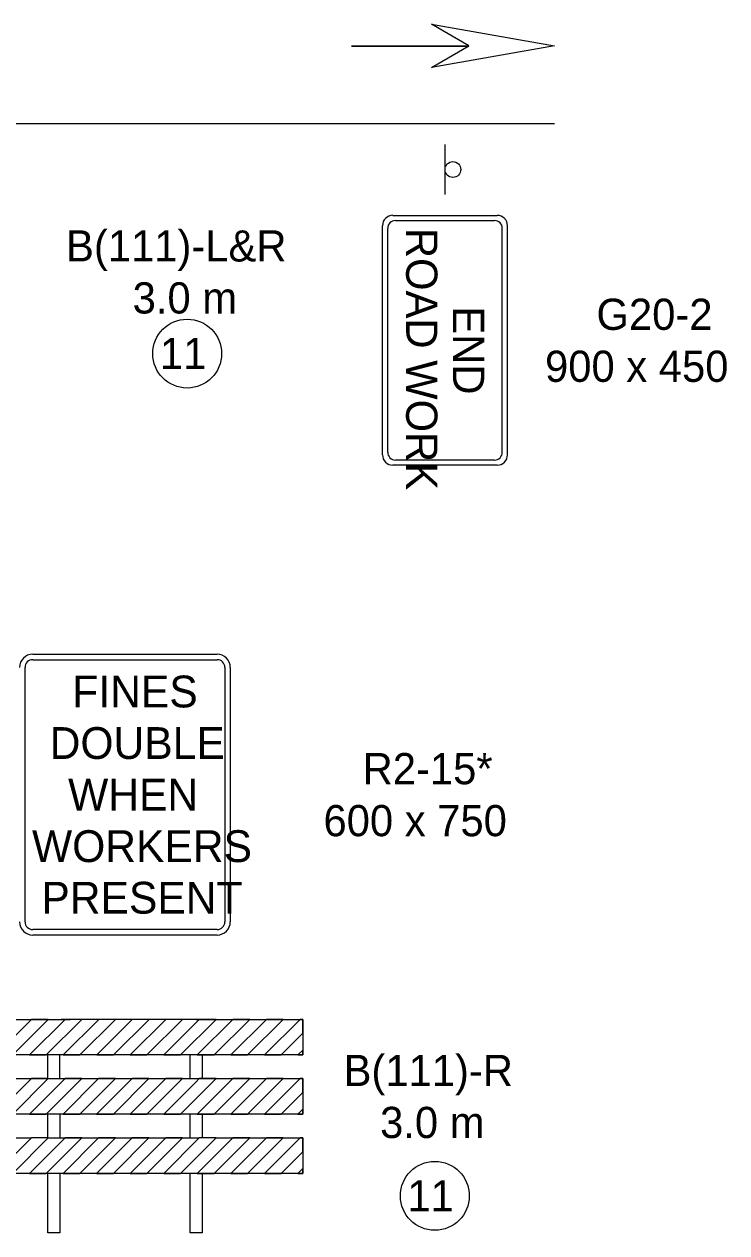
# Model space of a CAD drawing. Extents: x 49991.4 to 50021, y 49987.6 to 50011.4.
# Drawn here: x 50012.184 to 50013.534, y 49991.008 to 49993.332 of the extents above; entities that cross this region are included whole.
import ezdxf

# ---------------------------------------------------------------- set-up
doc = ezdxf.new("R2010")
doc.units = 0
for name, color, linetype in [('Level 1', 7, 'Continuous'), ('Level 2', 7, 'Continuous'), ('Level 3', 7, 'Continuous')]:
    doc.layers.add(name, color=color, linetype=linetype)

# ---------------------------------------------------------------- blocks, each defined once
blk = doc.blocks.new('G20-2')
at = {"layer": 'Level 1'}
for p, q in [((0.2197, 0.1196), (-0.2203, 0.1196)), ((-0.2403, -0.1004), (-0.2403, 0.0996)), ((-0.2303, -0.0954), (-0.2303, 0.0946)), ((0.2147, 0.1096), (-0.2153, 0.1096)), ((0.2297, 0.0946), (0.2297, -0.0954)), ((0.2397, 0.0996), (0.2397, -0.1004)), ((0.2147, -0.1104), (-0.2153, -0.1104)), ((0.2196, -0.1204), (-0.2204, -0.1204))]:
    blk.add_line(p, q, dxfattribs=at)
for centre, radius, start, end in [((-0.2203, 0.0996), 0.02, 90, 180), ((0.2197, 0.0996), 0.02, 360, 90), ((-0.2153, 0.0946), 0.015, 90, 180), ((0.2147, 0.0946), 0.015, 360, 90), ((-0.2204, -0.1004), 0.02, 180, 270), ((-0.2153, -0.0954), 0.015, 180, 270), ((0.2147, -0.0954), 0.015, 270, 360), ((0.2196, -0.1004), 0.02, 270, 360)]:
    blk.add_arc(centre, radius, start, end, dxfattribs=at)
for s, p in [('END', (-0.0655, 0.015)), ('ROAD WORK', (-0.2162, -0.075))]:
    blk.add_text(s, height=0.06, rotation=360, dxfattribs=at).set_placement(p)

msp = doc.modelspace()

# ---------------------------------------------------------------- linework, layer by layer
at = {"layer": 'Level 1'}
for p, q in [((50012.8131, 49993.2905), (50013.039, 49993.2905)), ((50012.8131, 49993.2901), (50013.039, 49993.2901)), ((50013.2032, 49993.1404), (50011.4032, 49993.1404)), ((50012.9929, 49993.0044), (50012.9929, 49993.1004)), ((50012.2007, 49992.1205), (50012.5551, 49992.1205)), ((50012.2007, 49992.11), (50012.5551, 49992.11)), ((50012.3779, 49992.1205), (50012.3779, 49992.1205)), ((50012.1859, 49991.6058), (50012.1859, 49992.0952)), ((50012.5699, 49992.0952), (50012.5699, 49991.6058)), ((50012.5804, 49992.0952), (50012.5804, 49991.6058)), ((50012.5551, 49991.591), (50012.2007, 49991.591)), ((50012.5551, 49991.5805), (50012.2007, 49991.5805)), ((50012.1301, 49991.3498), (50012.1985, 49991.4182)), ((50012.1985, 49991.4182), (50012.1301, 49991.3498)), ((50012.1623, 49991.3498), (50012.2307, 49991.4182)), ((50012.1623, 49991.3498), (50012.2307, 49991.4182)), ((50012.1946, 49991.3498), (50012.2629, 49991.4182)), ((50012.2268, 49991.3498), (50012.2952, 49991.4182)), ((50012.2411, 49991.4182), (50012.2724, 49991.4182)), ((50012.5004, 49991.4182), (50012.2554, 49991.4182)), ((50012.2592, 49991.3498), (50012.3276, 49991.4182)), ((50012.2914, 49991.3498), (50012.3598, 49991.4182)), ((50012.3236, 49991.3498), (50012.392, 49991.4182)), ((50012.3558, 49991.3498), (50012.4242, 49991.4182)), ((50012.3881, 49991.3498), (50012.4564, 49991.4182)), ((50012.4203, 49991.3498), (50012.4886, 49991.4182)), ((50012.4525, 49991.3498), (50012.5208, 49991.4182)), ((50012.5208, 49991.4182), (50012.481, 49991.4182)), ((50012.4847, 49991.3498), (50012.5531, 49991.4182)), ((50012.5169, 49991.3498), (50012.5853, 49991.4182)), ((50012.5853, 49991.4182), (50012.5169, 49991.3498)), ((50012.5492, 49991.3498), (50012.6176, 49991.4182)), ((50012.5492, 49991.3498), (50012.6176, 49991.4182)), ((50012.5814, 49991.3498), (50012.6498, 49991.4182)), ((50012.6498, 49991.4182), (50012.5814, 49991.3498)), ((50012.6136, 49991.3498), (50012.682, 49991.4182)), ((50012.6136, 49991.3498), (50012.682, 49991.4182)), ((50012.6459, 49991.3498), (50012.7143, 49991.4182)), ((50012.7143, 49991.4182), (50012.6459, 49991.3498)), ((50012.6781, 49991.3498), (50012.7199, 49991.3916)), ((50012.6781, 49991.3498), (50012.7199, 49991.3916)), ((50012.2525, 49991.3043), (50012.2525, 49991.3498)), ((50012.5033, 49991.3043), (50012.5033, 49991.3498)), ((50012.7104, 49991.3498), (50012.7199, 49991.3593)), ((50012.7199, 49991.3593), (50012.7104, 49991.3498)), ((50012.1301, 49991.2359), (50012.1985, 49991.3043)), ((50012.1985, 49991.3043), (50012.1301, 49991.2359)), ((50012.1623, 49991.2359), (50012.2307, 49991.3043)), ((50012.1623, 49991.2359), (50012.2307, 49991.3043)), ((50012.1946, 49991.2359), (50012.2629, 49991.3043)), ((50012.2268, 49991.2359), (50012.2952, 49991.3043)), ((50012.259, 49991.2359), (50012.3274, 49991.3043)), ((50012.2913, 49991.2359), (50012.3597, 49991.3043)), ((50012.3235, 49991.2359), (50012.3919, 49991.3043)), ((50012.3557, 49991.2359), (50012.4241, 49991.3043)), ((50012.388, 49991.2359), (50012.4564, 49991.3043)), ((50012.4202, 49991.2359), (50012.4886, 49991.3043)), ((50012.4525, 49991.2359), (50012.5147, 49991.2981)), ((50012.5147, 49991.2659), (50012.5531, 49991.3043)), ((50012.5147, 49991.2981), (50012.5208, 49991.3043)), ((50012.5169, 49991.2359), (50012.5853, 49991.3043)), ((50012.5853, 49991.3043), (50012.5169, 49991.2359)), ((50012.5492, 49991.2359), (50012.6176, 49991.3043)), ((50012.5492, 49991.2359), (50012.6176, 49991.3043)), ((50012.5814, 49991.2359), (50012.6498, 49991.3043)), ((50012.6498, 49991.3043), (50012.5814, 49991.2359)), ((50012.6136, 49991.2359), (50012.682, 49991.3043)), ((50012.6136, 49991.2359), (50012.682, 49991.3043)), ((50012.6459, 49991.2359), (50012.7143, 49991.3043)), ((50012.7143, 49991.3043), (50012.6459, 49991.2359)), ((50012.6781, 49991.2359), (50012.7199, 49991.2776)), ((50012.6781, 49991.2359), (50012.7199, 49991.2776)), ((50012.4847, 49991.2359), (50012.5147, 49991.2659)), ((50012.7104, 49991.2359), (50012.7199, 49991.2454)), ((50012.7199, 49991.2454), (50012.7104, 49991.2359)), ((50012.1301, 49991.1219), (50012.1985, 49991.1903)), ((50012.1985, 49991.1903), (50012.1301, 49991.1219)), ((50012.1623, 49991.1219), (50012.2307, 49991.1903)), ((50012.1623, 49991.1219), (50012.2307, 49991.1903)), ((50012.1946, 49991.1219), (50012.2629, 49991.1903)), ((50012.2629, 49991.1903), (50012.1946, 49991.1219)), ((50012.2268, 49991.1219), (50012.2952, 49991.1903)), ((50012.2268, 49991.1219), (50012.2952, 49991.1903)), ((50012.259, 49991.1219), (50012.3274, 49991.1903)), ((50012.3274, 49991.1903), (50012.259, 49991.1219)), ((50012.2913, 49991.1219), (50012.3597, 49991.1903)), ((50012.2913, 49991.1219), (50012.3597, 49991.1903)), ((50012.3235, 49991.1219), (50012.3919, 49991.1903)), ((50012.3919, 49991.1903), (50012.3235, 49991.1219)), ((50012.3557, 49991.1219), (50012.4241, 49991.1903)), ((50012.3557, 49991.1219), (50012.4241, 49991.1903)), ((50012.388, 49991.1219), (50012.4564, 49991.1903)), ((50012.4564, 49991.1903), (50012.388, 49991.1219)), ((50012.4202, 49991.1219), (50012.4886, 49991.1903)), ((50012.4202, 49991.1219), (50012.4886, 49991.1903)), ((50012.4525, 49991.1219), (50012.5208, 49991.1903)), ((50012.5208, 49991.1903), (50012.4525, 49991.1219)), ((50012.4847, 49991.1219), (50012.5531, 49991.1903)), ((50012.4847, 49991.1219), (50012.5531, 49991.1903)), ((50012.5169, 49991.1219), (50012.5853, 49991.1903)), ((50012.5853, 49991.1903), (50012.5169, 49991.1219)), ((50012.5492, 49991.1219), (50012.6176, 49991.1903)), ((50012.5492, 49991.1219), (50012.6176, 49991.1903)), ((50012.5814, 49991.1219), (50012.6498, 49991.1903)), ((50012.6498, 49991.1903), (50012.5814, 49991.1219)), ((50012.6136, 49991.1219), (50012.682, 49991.1903)), ((50012.6136, 49991.1219), (50012.682, 49991.1903)), ((50012.6459, 49991.1219), (50012.7143, 49991.1903)), ((50012.7143, 49991.1903), (50012.6459, 49991.1219)), ((50012.6781, 49991.1219), (50012.7199, 49991.1637)), ((50012.6781, 49991.1219), (50012.7199, 49991.1637)), ((50012.7104, 49991.1219), (50012.7199, 49991.1315)), ((50012.7199, 49991.1315), (50012.7104, 49991.1219))]:
    msp.add_line(p, q, dxfattribs=at)
msp.add_lwpolyline([(50012.9667, 49993.3321), (50013.2032, 49993.2905), (50012.9667, 49993.2485), (50013.0389, 49993.2905)], close=True, dxfattribs=at)
for points in [[(50012.5147, 49991.3498), (50012.0359, 49991.3498), (50012.0359, 49991.4182), (50012.2411, 49991.4182)], [(50012.2952, 49991.4182), (50012.2724, 49991.4182), (50012.2629, 49991.4182), (50012.1946, 49991.3498), (50012.2268, 49991.3498), (50012.2952, 49991.4182)], [(50012.2307, 49991.4182), (50012.1985, 49991.4182)], [(50012.3598, 49991.4182), (50012.3276, 49991.4182), (50012.2592, 49991.3498), (50012.2914, 49991.3498), (50012.3598, 49991.4182)], [(50012.4242, 49991.4182), (50012.392, 49991.4182), (50012.3236, 49991.3498), (50012.3558, 49991.3498), (50012.4242, 49991.4182)], [(50012.4886, 49991.4182), (50012.481, 49991.4182), (50012.4564, 49991.4182), (50012.3881, 49991.3498), (50012.4203, 49991.3498), (50012.4886, 49991.4182)], [(50012.4525, 49991.3498), (50012.4847, 49991.3498), (50012.5531, 49991.4182), (50012.5208, 49991.4182), (50012.4525, 49991.3498)], [(50012.5147, 49991.4182), (50012.7199, 49991.4182), (50012.7199, 49991.3498), (50012.5147, 49991.3498)], [(50012.6176, 49991.4182), (50012.5853, 49991.4182)], [(50012.682, 49991.4182), (50012.6498, 49991.4182)], [(50012.7199, 49991.3916), (50012.7199, 49991.4182), (50012.7143, 49991.4182)], [(50012.2297, 49991.3042), (50012.2297, 49991.3498)], [(50012.5169, 49991.3498), (50012.5492, 49991.3498)], [(50012.5261, 49991.3498), (50012.5261, 49991.3043)], [(50012.5814, 49991.3498), (50012.6136, 49991.3498)], [(50012.6459, 49991.3498), (50012.6781, 49991.3498)], [(50012.7104, 49991.3498), (50012.7199, 49991.3498), (50012.7199, 49991.3593)], [(50012.5147, 49991.3043), (50012.7199, 49991.3043), (50012.7199, 49991.2359), (50012.0359, 49991.2359), (50012.0359, 49991.3043), (50012.5147, 49991.3043)], [(50012.2952, 49991.3043), (50012.2629, 49991.3043), (50012.1946, 49991.2359), (50012.2268, 49991.2359), (50012.2952, 49991.3043)], [(50012.2307, 49991.3043), (50012.1985, 49991.3043)], [(50012.3597, 49991.3043), (50012.3274, 49991.3043), (50012.259, 49991.2359), (50012.2913, 49991.2359), (50012.3597, 49991.3043)], [(50012.4241, 49991.3043), (50012.3919, 49991.3043), (50012.3235, 49991.2359), (50012.3557, 49991.2359), (50012.4241, 49991.3043)], [(50012.4886, 49991.3043), (50012.4564, 49991.3043), (50012.388, 49991.2359), (50012.4202, 49991.2359), (50012.4886, 49991.3043)], [(50012.4525, 49991.2359), (50012.4847, 49991.2359), (50012.5147, 49991.2659), (50012.5531, 49991.3043), (50012.5261, 49991.3043), (50012.5208, 49991.3043), (50012.5147, 49991.2981), (50012.4525, 49991.2359)], [(50012.6176, 49991.3043), (50012.5853, 49991.3043)], [(50012.682, 49991.3043), (50012.6498, 49991.3043)], [(50012.7199, 49991.2776), (50012.7199, 49991.3043), (50012.7143, 49991.3043)], [(50012.2297, 49991.1903), (50012.2297, 49991.2359)], [(50012.2525, 49991.2359), (50012.2525, 49991.1903)], [(50012.5033, 49991.1903), (50012.5033, 49991.2359)], [(50012.5169, 49991.2359), (50012.5492, 49991.2359)], [(50012.5261, 49991.2359), (50012.5261, 49991.1903)], [(50012.5814, 49991.2359), (50012.6136, 49991.2359)], [(50012.6459, 49991.2359), (50012.6781, 49991.2359)], [(50012.7104, 49991.2359), (50012.7199, 49991.2359), (50012.7199, 49991.2454)], [(50012.5531, 49991.1903), (50012.7199, 49991.1903), (50012.7199, 49991.1219), (50012.0359, 49991.1219), (50012.0359, 49991.1903), (50012.1985, 49991.1903)], [(50012.2307, 49991.1903), (50012.1985, 49991.1903)], [(50012.2307, 49991.1903), (50012.5208, 49991.1903)], [(50012.2952, 49991.1903), (50012.2629, 49991.1903)], [(50012.3597, 49991.1903), (50012.3274, 49991.1903)], [(50012.4241, 49991.1903), (50012.3919, 49991.1903)], [(50012.4886, 49991.1903), (50012.4564, 49991.1903)], [(50012.5531, 49991.1903), (50012.5208, 49991.1903)], [(50012.6176, 49991.1903), (50012.5853, 49991.1903)], [(50012.682, 49991.1903), (50012.6498, 49991.1903)], [(50012.7199, 49991.1637), (50012.7199, 49991.1903), (50012.7143, 49991.1903)], [(50012.1946, 49991.1219), (50012.2268, 49991.1219)], [(50012.2525, 49991.1218), (50012.2525, 49991.0078), (50012.2297, 49991.0078), (50012.2297, 49991.1218)], [(50012.259, 49991.1219), (50012.2913, 49991.1219)], [(50012.3235, 49991.1219), (50012.3557, 49991.1219)], [(50012.388, 49991.1219), (50012.4202, 49991.1219)], [(50012.4525, 49991.1219), (50012.4847, 49991.1219)], [(50012.5261, 49991.1218), (50012.5261, 49991.0078), (50012.5033, 49991.0078), (50012.5033, 49991.1218)], [(50012.5169, 49991.1219), (50012.5492, 49991.1219)], [(50012.5814, 49991.1219), (50012.6136, 49991.1219)], [(50012.6459, 49991.1219), (50012.6781, 49991.1219)], [(50012.7104, 49991.1219), (50012.7199, 49991.1219), (50012.7199, 49991.1315)]]:
    msp.add_lwpolyline(points, dxfattribs=at)
msp.add_circle((50013.0081, 49993.0525), 0.0152, dxfattribs=at)
for centre, radius, start, end in [((50012.2007, 49992.0952), 0.0253, 90, 180), ((50012.2007, 49992.0952), 0.0148, 90, 180), ((50012.5551, 49992.0952), 0.0253, 0, 90), ((50012.5551, 49992.0952), 0.0148, 0, 90), ((50012.2007, 49991.6058), 0.0253, 180, 270), ((50012.2007, 49991.6058), 0.0148, 180, 270), ((50012.5551, 49991.6058), 0.0148, 270, 360), ((50012.5551, 49991.6058), 0.0253, 270, 360)]:
    msp.add_arc(centre, radius, start, end, dxfattribs=at)
at = {"layer": 'Level 2'}
for centre in [(50012.4975, 49992.6986), (50012.9734, 49991.0789)]:
    msp.add_circle(centre, 0.0662, dxfattribs=at)

# ---------------------------------------------------------------- block references
at = {"layer": 'Level 3', "xscale": 1.001, "yscale": 1.001, "rotation": -90.00000000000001}
msp.add_blockref('G20-2', (50012.9933, 49992.7239), dxfattribs=at)

# ---------------------------------------------------------------- texts
at = {"layer": 'Level 1'}
for s, p in [('FINES', (50012.2768, 49992.0182)), ('DOUBLE', (50012.2333, 49991.9191)), ('WHEN', (50012.2687, 49991.8199)), ('WORKERS', (50012.1993, 49991.7208)), ('PRESENT', (50012.2174, 49991.6216))]:
    msp.add_text(s, height=0.06118, dxfattribs=at).set_placement(p)
at = {"layer": 'Level 2'}
for s, height, p in [('B(111)-L&R', 0.06, (50012.2648, 49992.8757)), ('3.0 m', 0.06, (50012.3927, 49992.7757)), ('G20-2', 0.06, (50013.2839, 49992.7442)), ('11', 0.06006, (50012.4451, 49992.6687)), ('900 x 450', 0.06, (50013.1851, 49992.6442)), ('R2-15*', 0.06, (50012.8346, 49991.8705)), ('600 x 750', 0.06, (50012.7594, 49991.7705)), ('B(111)-R', 0.06, (50012.798, 49991.2901)), ('3.0 m', 0.06, (50012.8682, 49991.1901)), ('11', 0.06006, (50012.9205, 49991.0489))]:
    msp.add_text(s, height=height, dxfattribs=at).set_placement(p)

doc.saveas('drawing.dxf')
